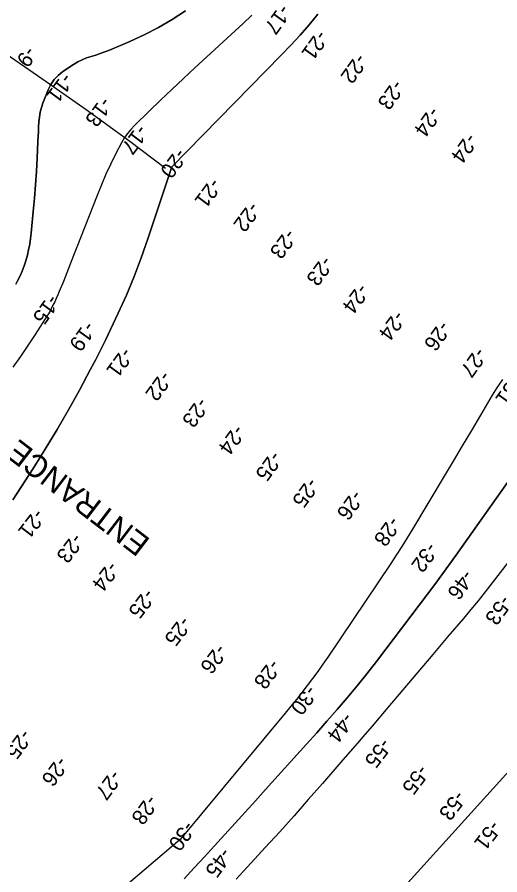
# Model space of a CAD drawing. Extents: x 3879599 to 3900814, y 146526 to 168888.
# Drawn here: x 3890077 to 3891140, y 154174 to 156064 of the extents above; entities that cross this region are included whole.
import ezdxf

# ---------------------------------------------------------------- set-up
doc = ezdxf.new("R2010")
doc.units = 0
for name, color, linetype in [('V-CHAN-NAID', 7, 'Continuous'), ('V-LEVE-TOET', 7, 'Continuous'), ('V-RIVR-RANG', 7, 'Continuous'), ('V-TOPO-DPTH', 7, 'Continuous'), ('V-TOPO-MAJR', 7, 'Continuous'), ('V-TOPO-MINR', 7, 'Continuous')]:
    doc.layers.add(name, color=color, linetype=linetype)

msp = doc.modelspace()

# ---------------------------------------------------------------- linework, layer by layer
at = {"layer": 'V-LEVE-TOET'}
msp.add_lwpolyline([(3890403.6, 155730.2), (3890324.9, 155789.6), (3890228.5, 155859.5), (3890140.2, 155921.2), (3890023.2, 156001.7), (3889936.4, 156072.9), (3889903.3, 156102.9), (3889830, 156175.1), (3889749.8, 156256.5), (3889673, 156327.5), (3889604.8, 156383.4), (3889506.1, 156470.1), (3889457.7, 156508.3)], dxfattribs=at)
at = {"layer": 'V-RIVR-RANG'}
msp.add_lwpolyline([(3887950.4, 150855.4), (3895383.9, 159071.9)], dxfattribs=at)
at = {"layer": 'V-TOPO-DPTH'}
for points in [[(3890073.9, 155475.6), (3890076.9, 155481.6), (3890082.3, 155492.6), (3890087.4, 155504), (3890091.9, 155515.5), (3890095.8, 155527.2), (3890099.2, 155539.2), (3890101.9, 155551.3), (3890104.2, 155563.5), (3890106.1, 155575.8), (3890107.5, 155588.1), (3890112.1, 155635.8), (3890114.7, 155665.1), (3890117, 155694.3), (3890118.9, 155723.6), (3890120.5, 155752.9), (3890122.4, 155790.1), (3890122.9, 155800.9), (3890123.4, 155811.6), (3890123.9, 155822.3), (3890124.4, 155833.1), (3890125.5, 155843.7), (3890127.2, 155854.2), (3890129.9, 155864.4), (3890133.3, 155874.5), (3890144.9, 155903.8), (3890150.8, 155915.5), (3890158, 155926.2), (3890166.9, 155935.5), (3890177.1, 155943.7), (3890201.1, 155959.7), (3890210.2, 155965.2), (3890219.6, 155970), (3890229.4, 155973.9), (3890239.5, 155977.3), (3890249.8, 155980.3), (3890259.9, 155983.6), (3890270, 155987.3), (3890279.9, 155991.2), (3890325, 156010.2), (3890356.9, 156024.8), (3890388.1, 156040.7), (3890418.2, 156058.5), (3890447.7, 156077.6)], [(3890739.4, 156070.2), (3890719.9, 156047), (3890700.1, 156024.1), (3890679.6, 156001.8), (3890658.7, 155979.9), (3890417.4, 155734.2), (3890364.8, 155575.1), (3890350.2, 155533.5), (3890334.6, 155492.2), (3890317.6, 155451.5), (3890299.5, 155411.3), (3890282.7, 155375.6), (3890272.1, 155353.6), (3890261.3, 155331.6), (3890250.1, 155309.8), (3890238.6, 155288.2), (3890213.8, 155242.2), (3890189.5, 155198.3), (3890164.5, 155154.9), (3890138.5, 155112), (3890111.9, 155069.5), (3890076.9, 155015), (3890066.9, 155000.3)], [(3890066.9, 155000.3), (3890076.9, 155015), (3890111.9, 155069.5), (3890138.5, 155112), (3890164.5, 155154.9), (3890189.5, 155198.3), (3890213.8, 155242.2), (3890238.6, 155288.2), (3890250.1, 155309.8), (3890261.3, 155331.6), (3890272.1, 155353.6), (3890282.7, 155375.6), (3890299.5, 155411.3), (3890317.6, 155451.5), (3890334.6, 155492.2), (3890350.2, 155533.5), (3890364.8, 155575.1), (3890417.4, 155734.2), (3890658.7, 155979.9), (3890679.6, 156001.8), (3890700.1, 156024.1), (3890719.9, 156047), (3890739.4, 156070.2)], [(3891146.2, 155265.3), (3891138.4, 155254), (3891130.9, 155242.4), (3891123.7, 155230.7), (3891097.8, 155186.9), (3891077.7, 155153.2), (3891057.7, 155119.5), (3891037.6, 155085.8), (3891017.6, 155052.1), (3890948, 154935.5), (3890936.3, 154916.4), (3890924.5, 154897.4), (3890912.3, 154878.6), (3890900, 154859.9), (3890761.1, 154653.9), (3890750.2, 154638), (3890739, 154622.1), (3890727.5, 154606.4), (3890715.9, 154590.9), (3890704, 154575.6), (3890692, 154560.3), (3890679.8, 154545.3), (3890667.5, 154530.3), (3890435.7, 154251.9), (3890242.5, 154087.6)], [(3891146.2, 155265.3), (3891138.4, 155254), (3891130.9, 155242.4), (3891123.7, 155230.7), (3891097.8, 155186.9), (3891077.7, 155153.2), (3891057.7, 155119.5), (3891037.6, 155085.8), (3891017.6, 155052.1), (3890948, 154935.5), (3890936.3, 154916.4), (3890924.5, 154897.4), (3890912.3, 154878.6), (3890900, 154859.9), (3890761.1, 154653.9), (3890750.2, 154638), (3890739, 154622.1), (3890727.5, 154606.4), (3890715.9, 154590.9), (3890704, 154575.6), (3890692, 154560.3), (3890679.8, 154545.3), (3890667.5, 154530.3), (3890435.7, 154251.9), (3890242.5, 154087.6)], [(3890444.8, 154165.5), (3890467.1, 154189.7), (3890489.4, 154213.9), (3890511.6, 154238.2), (3890533.8, 154262.5), (3890534.4, 154263.1), (3890556.8, 154287.7), (3890579.2, 154312.3), (3890601.6, 154337), (3890624, 154361.7), (3890714.4, 154461.6), (3890737, 154486.9), (3890759.4, 154512.4), (3890781.6, 154538.1), (3890803.6, 154564), (3890803.9, 154564.3), (3890825.7, 154590.7), (3890847.2, 154617.2), (3890868.3, 154644.1), (3890889.1, 154671.1), (3890981.2, 154792.7), (3890997, 154813.7), (3891012.6, 154834.7), (3891028, 154856), (3891043.3, 154877.3), (3891178.5, 155068.3)], [(3890444.8, 154165.5), (3890467.1, 154189.7), (3890489.4, 154213.9), (3890511.6, 154238.2), (3890533.8, 154262.5), (3890534.4, 154263.1), (3890556.8, 154287.7), (3890579.2, 154312.3), (3890601.6, 154337), (3890624, 154361.7), (3890714.4, 154461.6), (3890737, 154486.9), (3890759.4, 154512.4), (3890781.6, 154538.1), (3890803.6, 154564), (3890803.9, 154564.3), (3890825.7, 154590.7), (3890847.2, 154617.2), (3890868.3, 154644.1), (3890889.1, 154671.1), (3890981.2, 154792.7), (3890997, 154813.7), (3891012.6, 154834.7), (3891028, 154856), (3891043.3, 154877.3), (3891178.5, 155068.3)]]:
    msp.add_lwpolyline(points, dxfattribs=at)
at = {"layer": 'V-TOPO-MAJR'}
msp.add_lwpolyline([(3891234.7, 154960.9), (3891123.9, 154817.7), (3891108.3, 154797.8), (3891092.4, 154778), (3891076.4, 154758.4), (3891060.1, 154739), (3891026.1, 154699), (3890992.9, 154659.8), (3890959.7, 154620.7), (3890926.5, 154581.6), (3890893.3, 154542.5), (3890858.7, 154501.8), (3890842.8, 154483.1), (3890826.8, 154464.4), (3890810.7, 154445.8), (3890794.6, 154427.3), (3890749.4, 154375.3), (3890718.2, 154339.7), (3890686.8, 154304.3), (3890655.2, 154269.1), (3890623.4, 154234.1), (3890592.2, 154200.1), (3890575.8, 154182.2), (3890559.5, 154164.3)], dxfattribs=at)
at = {"layer": 'V-TOPO-MINR'}
for points in [[(3890447.7, 156077.6), (3890418.2, 156058.5), (3890388.1, 156040.7), (3890356.9, 156024.8), (3890325, 156010.2), (3890279.9, 155991.2), (3890270, 155987.3), (3890259.9, 155983.6), (3890249.8, 155980.3), (3890239.5, 155977.3), (3890229.4, 155973.9), (3890219.6, 155970), (3890210.2, 155965.2), (3890201.1, 155959.7), (3890177.1, 155943.7), (3890166.9, 155935.5), (3890158, 155926.2), (3890150.8, 155915.5), (3890144.9, 155903.8), (3890133.3, 155874.5), (3890129.9, 155864.4), (3890127.2, 155854.2), (3890125.5, 155843.7), (3890124.4, 155833.1), (3890123.9, 155822.3), (3890123.4, 155811.6), (3890122.9, 155800.9), (3890122.4, 155790.1), (3890120.5, 155752.9), (3890118.9, 155723.6), (3890117, 155694.3), (3890114.7, 155665.1), (3890112.1, 155635.8), (3890107.5, 155588.1), (3890106.1, 155575.8), (3890104.2, 155563.5), (3890101.9, 155551.3), (3890099.2, 155539.2), (3890095.8, 155527.2), (3890091.9, 155515.5), (3890087.4, 155504), (3890082.3, 155492.6), (3890076.9, 155481.6), (3890073.9, 155475.6)], [(3890739.4, 156070.2), (3890719.9, 156047), (3890700.1, 156024.1), (3890679.6, 156001.8), (3890658.7, 155979.9), (3890417.4, 155734.2), (3890364.8, 155575.1), (3890350.2, 155533.5), (3890334.6, 155492.2), (3890317.6, 155451.5), (3890299.5, 155411.3), (3890282.7, 155375.6), (3890272.1, 155353.6), (3890261.3, 155331.6), (3890250.1, 155309.8), (3890238.6, 155288.2), (3890213.8, 155242.2), (3890189.5, 155198.3), (3890164.5, 155154.9), (3890138.5, 155112), (3890111.9, 155069.5), (3890076.9, 155015), (3890066.9, 155000.3)], [(3890593.8, 156068), (3890574.6, 156049.7), (3890468.5, 155951.9), (3890443, 155928.3), (3890417.7, 155904.5), (3890392.6, 155880.5), (3890367.6, 155856.4), (3890335, 155824.7), (3890326.9, 155816), (3890319.3, 155806.8), (3890312.7, 155797), (3890306.7, 155786.7), (3890294.4, 155763.1), (3890283.1, 155740.5), (3890272.3, 155717.7), (3890262.2, 155694.5), (3890252.7, 155671.1), (3890208.5, 155557.2), (3890201.1, 155538.3), (3890193.6, 155519.3), (3890186, 155500.4), (3890178.4, 155481.5), (3890169.5, 155459.4), (3890166.2, 155451.6), (3890162.8, 155443.9), (3890159.3, 155436.3), (3890155.5, 155428.8), (3890151.7, 155421.3), (3890149.8, 155417.6), (3890147.8, 155413.9), (3890145.6, 155410.4), (3890143.5, 155406.8), (3890116.5, 155364.7), (3890100.5, 155340.3), (3890084.1, 155316.1), (3890067.3, 155292.3)], [(3891146.2, 155265.3), (3891138.4, 155254), (3891130.9, 155242.4), (3891123.7, 155230.7), (3891097.8, 155186.9), (3891077.7, 155153.2), (3891057.7, 155119.5), (3891037.6, 155085.8), (3891017.6, 155052.1), (3890948, 154935.5), (3890936.3, 154916.4), (3890924.5, 154897.4), (3890912.3, 154878.6), (3890900, 154859.9), (3890761.1, 154653.9), (3890750.2, 154638), (3890739, 154622.1), (3890727.5, 154606.4), (3890715.9, 154590.9), (3890704, 154575.6), (3890692, 154560.3), (3890679.8, 154545.3), (3890667.5, 154530.3), (3890435.7, 154251.9), (3890242.5, 154087.6)], [(3891178.5, 155068.3), (3891043.3, 154877.3), (3891028, 154856), (3891012.6, 154834.7), (3890997, 154813.7), (3890981.2, 154792.7), (3890889.1, 154671.1), (3890868.3, 154644.1), (3890847.2, 154617.2), (3890825.7, 154590.7), (3890803.9, 154564.3), (3890803.6, 154564), (3890781.6, 154538.1), (3890759.4, 154512.4), (3890737, 154486.9), (3890714.4, 154461.6), (3890624, 154361.7), (3890601.6, 154337), (3890579.2, 154312.3), (3890556.8, 154287.7), (3890534.4, 154263.1), (3890533.8, 154262.5), (3890511.6, 154238.2), (3890489.4, 154213.9), (3890467.1, 154189.7), (3890444.8, 154165.5)]]:
    msp.add_lwpolyline(points, dxfattribs=at)

# ---------------------------------------------------------------- texts
at = {"layer": 'V-CHAN-NAID'}
msp.add_text('ENTRANCE "A" RANGE EAST FRONT', height=50, rotation=142.6154, dxfattribs=at).set_placement((3890372.4, 154912.4))
at = {"layer": 'V-RIVR-RANG'}
for s, rotation, p in [('-17', 234.3083, (3890657.1, 156094.4)), ('-21', 234.3083, (3890739.3, 156037.5)), ('-9', 233.3283, (3890097.2, 156002)), ('-22', 234.3083, (3890825.5, 155986.1)), ('-11', 233.3283, (3890178.1, 155943.1)), ('-23', 234.3083, (3890907, 155928.2)), ('-13', 233.3283, (3890263.5, 155890.4)), ('-24', 234.3083, (3890987.4, 155868.6)), ('-17', 233.3283, (3890342.9, 155829.6)), ('-24', 234.3083, (3891068.8, 155810.5)), ('-20', 233.3283, (3890428.6, 155777.2)), ('-21', 233.3283, (3890504.5, 155711.7)), ('-22', 233.3283, (3890589.8, 155658.9)), ('-23', 233.3283, (3890670.3, 155599.6)), ('-23', 233.3283, (3890750.7, 155540)), ('-24', 233.3283, (3890830, 155479.1)), ('-15', 233.9383, (3890147.2, 155455.3)), ('-24', 233.3283, (3890910.3, 155419.6)), ('-19', 233.9383, (3890227.6, 155395.9)), ('-26', 234.4529, (3891009.2, 155396.8)), ('-21', 233.9383, (3890309.5, 155338.5)), ('-27', 234.4529, (3891088.8, 155338.6)), ('-22', 233.9383, (3890395.4, 155286.6)), ('-31', 234.4529, (3891166.5, 155276.1)), ('-23', 233.9383, (3890476.5, 155228.1)), ('-24', 233.9383, (3890556.5, 155168.1)), ('-25', 233.9383, (3890638, 155110.1)), ('-25', 233.9383, (3890719, 155051.5)), ('-26', 234.0789, (3890817.2, 155024)), ('-21', 232.4783, (3890116.1, 154983)), ('-28', 234.0789, (3890899, 154966.1)), ('-23', 232.4783, (3890200.7, 154929.1)), ('-32', 234.0789, (3890981.4, 154909)), ('-24', 232.4783, (3890279.2, 154867)), ('-46', 234.0789, (3891061, 154848.6)), ('-25', 232.4783, (3890359.2, 154807)), ('-53', 234.0789, (3891144.1, 154792.7)), ('-25', 232.4783, (3890438.6, 154746.3)), ('-26', 232.4783, (3890517.6, 154684.9)), ('-28', 232.6215, (3890635.6, 154651.4)), ('-30', 232.6215, (3890716.4, 154594.4)), ('-44', 232.6215, (3890797.2, 154534)), ('-25', 233.5583, (3890086.9, 154497.2)), ('-55', 232.6215, (3890879.7, 154477.7)), ('-26', 233.5583, (3890167, 154437.4)), ('-27', 233.6983, (3890284.9, 154407.5)), ('-55', 232.6215, (3890962.3, 154418.9)), ('-28', 233.6983, (3890364.9, 154352.6)), ('-53', 232.6215, (3891043.6, 154362.1)), ('-30', 233.6983, (3890446.7, 154295.1)), ('-51', 232.6215, (3891121.2, 154296.3)), ('-45', 233.6983, (3890527.5, 154236.2))]:
    msp.add_text(s, height=33.5, rotation=rotation, dxfattribs=at).set_placement(p)

doc.saveas('drawing.dxf')
